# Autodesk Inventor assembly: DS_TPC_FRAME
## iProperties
Shininess: 64.0
Length Units: 11272
Angle Units: 11279
Time Units: 11290
Mass Units: 11286
Length Display Precision: 3
Angle Display Precision: 2
Compacted: True
Part Number: DS_TPC_FRAME
Document SubType Name: Assembly
Created: 2004-08
Designer: John Blackburn
Manufacturer: Standard
Standards Organization: Custom
Density: 0.0
Volumn: 0.0
Area: 0.0
PropertySet Name: Model Information
Control State: 0
Master: False
Checked Out: False
Author: John Blackburn
